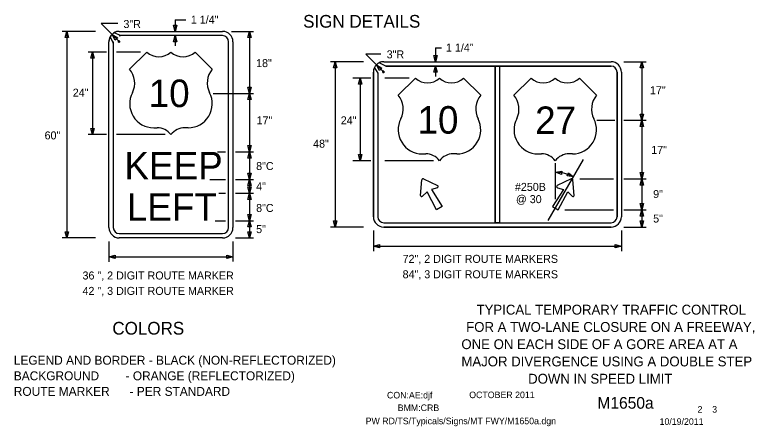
# Model space of a CAD drawing. Extents: x 16512 to 19509, y 5761 to 6974.
# Drawn here: x 17768 to 18466, y 5932 to 6320 of the extents above; entities that cross this region are included whole.
import ezdxf

# ---------------------------------------------------------------- set-up
doc = ezdxf.new("R2010")
doc.units = 0
for name, color, linetype in [('BORDER', 7, 'Continuous'), ('BORDER_SIGNAL_WO', 7, 'Continuous'), ('TRAFFIC_SIGNS_PR', 7, 'Continuous'), ('TYPICAL_EX', 7, 'Continuous'), ('TYPICAL_TEXT_DIMEN_PR', 7, 'Continuous')]:
    doc.layers.add(name, color=color, linetype=linetype)

msp = doc.modelspace()

# ---------------------------------------------------------------- linework, layer by layer
at = {"layer": 'TRAFFIC_SIGNS_PR'}
for p, q in [((17859.5, 6300.96), (17858.5, 6299.45)), ((17868.29, 6300.52), (17862.19, 6303.27)), ((17867.09, 6304.58), (17964.59, 6304.58)), ((17857.34, 6119.33), (17857.34, 6294.83)), ((17858.53, 6299.39), (17861.4, 6293.35)), ((17861.4, 6294.83), (17861.4, 6119.33)), ((17964.59, 6300.52), (17867.09, 6300.52)), ((17970.27, 6119.33), (17970.27, 6294.83)), ((17974.34, 6294.83), (17974.34, 6119.33)), ((18118.56, 6271.83), (18112.33, 6274.85)), ((18116.61, 6275.88), (18331.11, 6275.88)), ((18116.61, 6275.88), (18331.11, 6275.88)), ((18106.86, 6266.13), (18106.86, 6129.63)), ((18106.86, 6129.63), (18106.86, 6266.13)), ((18107.78, 6270.14), (18110.91, 6265.1)), ((18118.55, 6271.82), (18221.83, 6271.82)), ((18331.11, 6271.82), (18118.55, 6271.82)), ((18221.83, 6271.82), (18221.83, 6123.95)), ((18225.89, 6271.82), (18225.89, 6123.95)), ((18225.89, 6271.82), (18331.11, 6271.82)), ((18336.8, 6266.13), (18336.8, 6220.38)), ((18336.8, 6129.63), (18336.8, 6266.13)), ((18340.86, 6266.13), (18340.86, 6129.63)), ((18340.86, 6266.13), (18340.86, 6129.63)), ((18110.92, 6265.08), (18110.92, 6129.63)), ((18110.92, 6265.08), (18110.92, 6129.63)), ((18336.8, 6220.38), (18336.8, 6129.63)), ((18151.46, 6149.74), (18152.61, 6164.46)), ((18154.12, 6165.33), (18167.44, 6158.97)), ((18293.59, 6165.33), (18280.28, 6158.97)), ((18296.26, 6149.74), (18295.1, 6164.46)), ((18116.61, 6123.95), (18331.11, 6123.95)), ((18116.61, 6119.88), (18331.11, 6119.88)), ((18331.11, 6119.88), (18116.61, 6119.88)), ((17867.09, 6113.64), (17964.59, 6113.64)), ((17964.59, 6109.58), (17867.09, 6109.58))]:
    msp.add_line(p, q, dxfattribs=at)
for points in [[(18118.55, 6271.82), (18118.53, 6271.83)], [(18110.91, 6265.1), (18110.92, 6265.08)], [(18167.28, 6157), (18161.55, 6155.42), (18171.77, 6139.25), (18166.37, 6136.13), (18157.48, 6153.07), (18153.25, 6148.9)], [(18280.44, 6157), (18286.16, 6155.42), (18275.95, 6139.25), (18281.34, 6136.13), (18290.24, 6153.07), (18294.46, 6148.9)]]:
    msp.add_lwpolyline(points, dxfattribs=at)
msp.add_lwpolyline([(18221.83, 6271.82), (18225.89, 6271.82), (18225.89, 6123.95), (18221.83, 6123.95)], close=True, dxfattribs=at)
for centre, radius, start, end in [((17867.09, 6294.83), 9.75, 90, 180), ((17866.5, 6297.01), 7.6, 85.58319, 124.53531), ((17964.59, 6294.83), 9.75, 0, 90), ((17864.37, 6295.43), 7.06, 145.86811, 184.82317), ((17855.94, 6294.09), 5.51, 352.24294, 7.75653), ((17867.69, 6304.95), 4.47, 262.2432, 277.7568), ((17964.59, 6294.83), 5.69, 0, 90), ((18116.61, 6266.13), 9.75, 90, 180), ((18116.61, 6266.13), 9.75, 90, 180), ((18115.93, 6269.32), 6.6, 84.11162, 123.06374), ((18331.11, 6266.13), 9.75, 0, 90), ((18331.11, 6266.13), 9.75, 0, 90), ((18112.99, 6266.84), 6.17, 147.60925, 186.56283), ((18117.55, 6279), 7.24, 277.81035, 278.05403), ((18331.11, 6266.13), 5.69, 0, 89.99421), ((18331.11, 6266.13), 5.69, 0, 90), ((18153.67, 6164.37), 1.06, 64.48226, 175.51774), ((18294.05, 6164.37), 1.06, 4.48226, 115.51774), ((18166.98, 6158.02), 1.06, 285.9885, 64.48226), ((18280.73, 6158.02), 1.06, 115.51774, 254.0115), ((18152.52, 6149.66), 1.06, 175.51775, 314.01151), ((18295.2, 6149.66), 1.06, 225.98849, 4.48225), ((18116.61, 6129.63), 9.75, 180, 270), ((18116.61, 6129.63), 9.75, 180, 270), ((18116.61, 6129.63), 5.69, 180, 270), ((18116.61, 6129.63), 5.69, 180, 270), ((18331.11, 6129.63), 9.75, 270, 0), ((18331.11, 6129.63), 5.69, 270, 0), ((18331.11, 6129.63), 9.75, 270, 0), ((18331.11, 6129.63), 5.69, 270, 0), ((17867.09, 6119.33), 9.75, 180, 270), ((17867.09, 6119.33), 5.69, 180, 270), ((17964.59, 6119.33), 5.69, 270, 0), ((17964.59, 6119.33), 9.75, 270, 0)]:
    msp.add_arc(centre, radius, start, end, dxfattribs=at)
at = {"layer": 'TYPICAL_EX'}
for p, q in [((17876.84, 6268.84), (17893.09, 6285.09)), ((17954.84, 6268.84), (17938.59, 6285.09)), ((18130.22, 6244.22), (18146.47, 6260.47)), ((18208.22, 6244.22), (18191.97, 6260.47)), ((18239.5, 6244.22), (18255.75, 6260.47)), ((18317.5, 6244.22), (18301.25, 6260.47)), ((17899.56, 6213.54), (17902.81, 6213.54)), ((17932.11, 6213.54), (17928.86, 6213.54)), ((18152.95, 6188.93), (18156.2, 6188.93)), ((18185.49, 6188.93), (18182.24, 6188.93)), ((18262.22, 6188.93), (18265.47, 6188.93)), ((18294.77, 6188.93), (18291.52, 6188.93))]:
    msp.add_line(p, q, dxfattribs=at)
for centre, radius, start, end in [((17904.46, 6296.92), 16.42, 226.14041, 313.85958), ((17927.21, 6296.92), 16.42, 226.14042, 313.85959), ((17861.44, 6255.82), 20.16, 333.09768, 40.19361), ((17970.24, 6255.82), 20.16, 139.80639, 206.90233), ((18157.85, 6272.31), 16.42, 226.14041, 313.85958), ((18180.59, 6272.31), 16.42, 226.14042, 313.85959), ((18267.12, 6272.31), 16.42, 226.14041, 313.85958), ((18289.87, 6272.31), 16.42, 226.14042, 313.85959), ((17899.6, 6236.27), 22.73, 152.6698, 269.90132), ((17932.07, 6236.27), 22.73, 270.09868, 27.3302), ((18114.82, 6231.21), 20.16, 333.09768, 40.19361), ((18223.62, 6231.21), 20.16, 139.80639, 206.90233), ((18224.1, 6231.21), 20.16, 333.09768, 40.19361), ((18332.9, 6231.21), 20.16, 139.80639, 206.90233), ((18152.99, 6211.66), 22.73, 152.6698, 269.90132), ((18185.45, 6211.66), 22.73, 270.09868, 27.3302), ((18262.27, 6211.66), 22.73, 152.6698, 269.90132), ((18294.73, 6211.66), 22.73, 270.09868, 27.3302), ((17902.85, 6197.26), 16.28, 37.1038, 90.13853), ((17928.82, 6197.26), 16.28, 89.86147, 142.8962), ((18156.24, 6172.65), 16.28, 37.1038, 90.13853), ((18182.2, 6172.65), 16.28, 89.86147, 142.8962), ((18265.52, 6172.65), 16.28, 37.1038, 90.13853), ((18291.48, 6172.65), 16.28, 89.86147, 142.8962)]:
    msp.add_arc(centre, radius, start, end, dxfattribs=at)
at = {"layer": 'TYPICAL_TEXT_DIMEN_PR'}
for p, q in [((17919.81, 6315.34), (17919.81, 6304.58)), ((17919.81, 6315.34), (17929.91, 6315.34)), ((17865.71, 6311.86), (17850.05, 6311.86)), ((17850.05, 6311.86), (17860.29, 6301.63)), ((17919.81, 6304.58), (17918.24, 6310.44)), ((17918.24, 6310.44), (17919.81, 6310.44)), ((17919.81, 6310.44), (17921.38, 6310.44)), ((17921.38, 6310.44), (17919.81, 6304.58)), ((17844.51, 6304.58), (17813.21, 6304.58)), ((17815.98, 6298.72), (17817.55, 6304.58)), ((17817.55, 6304.58), (17817.55, 6109.58)), ((17817.55, 6304.58), (17819.12, 6298.72)), ((17860.29, 6301.63), (17866.85, 6295.07)), ((17863.32, 6296.37), (17860.29, 6301.63)), ((17860.29, 6301.63), (17865.54, 6298.6)), ((17972.88, 6304.58), (17993.84, 6304.58)), ((17988.37, 6298.72), (17989.94, 6304.58)), ((17989.94, 6304.58), (17989.94, 6246.08)), ((17989.94, 6304.58), (17991.51, 6298.72)), ((17817.55, 6298.72), (17815.98, 6298.72)), ((17819.12, 6298.72), (17817.55, 6298.72)), ((17864.43, 6297.49), (17863.32, 6296.37)), ((17865.54, 6298.6), (17864.43, 6297.49)), ((17865.64, 6295.07), (17868.05, 6295.07)), ((17866.85, 6293.86), (17866.85, 6296.28)), ((17918.28, 6294.66), (17919.86, 6300.52)), ((17919.86, 6294.66), (17918.28, 6294.66)), ((17919.86, 6300.52), (17919.86, 6290.77)), ((17919.86, 6300.52), (17921.43, 6294.66)), ((17921.43, 6294.66), (17919.86, 6294.66)), ((17989.94, 6298.72), (17988.37, 6298.72)), ((17991.51, 6298.72), (17989.94, 6298.72)), ((18165.47, 6289.03), (18165.47, 6275.88)), ((18165.47, 6289.03), (18170.99, 6289.03)), ((17854.96, 6285.08), (17837.84, 6285.08)), ((17840.16, 6279.22), (17841.73, 6285.08)), ((17841.73, 6285.08), (17841.73, 6207.08)), ((17841.73, 6285.08), (17843.3, 6279.22)), ((17887.2, 6285.08), (17864.33, 6285.08)), ((18113.75, 6283.17), (18099.57, 6283.17)), ((18099.57, 6283.17), (18109.72, 6273.02)), ((18165.47, 6275.88), (18163.89, 6281.74)), ((18163.89, 6281.74), (18165.47, 6281.74)), ((18165.47, 6281.74), (18167.04, 6281.74)), ((18167.04, 6281.74), (18165.47, 6275.88)), ((17841.73, 6279.22), (17840.16, 6279.22)), ((17843.3, 6279.22), (17841.73, 6279.22)), ((18097.62, 6275.88), (18066.33, 6275.88)), ((18069.1, 6270.02), (18070.67, 6275.88)), ((18070.67, 6275.88), (18070.67, 6119.88)), ((18070.67, 6275.88), (18072.24, 6270.02)), ((18109.72, 6273.02), (18116.37, 6266.37)), ((18112.76, 6267.76), (18109.72, 6273.02)), ((18109.72, 6273.02), (18114.98, 6269.99)), ((18343.23, 6275.88), (18364.19, 6275.88)), ((18358.72, 6270.02), (18360.29, 6275.88)), ((18360.29, 6275.88), (18360.29, 6220.63)), ((18360.29, 6275.88), (18361.86, 6270.02)), ((18070.67, 6270.02), (18069.1, 6270.02)), ((18072.24, 6270.02), (18070.67, 6270.02)), ((18113.87, 6268.88), (18112.76, 6267.76)), ((18114.98, 6269.99), (18113.87, 6268.88)), ((18115.16, 6266.37), (18117.58, 6266.37)), ((18116.37, 6265.16), (18116.37, 6267.58)), ((18163.94, 6265.96), (18165.51, 6271.82)), ((18163.94, 6265.96), (18165.51, 6271.82)), ((18165.51, 6271.82), (18165.51, 6262.07)), ((18165.51, 6271.82), (18167.08, 6265.96)), ((18165.51, 6271.82), (18167.08, 6265.96)), ((18360.29, 6270.02), (18358.72, 6270.02)), ((18361.86, 6270.02), (18360.29, 6270.02)), ((18104.49, 6260.47), (18087.36, 6260.47)), ((18092.65, 6254.61), (18094.23, 6260.47)), ((18094.23, 6260.47), (18094.23, 6182.47)), ((18094.23, 6260.47), (18095.8, 6254.61)), ((18140.59, 6260.47), (18117.71, 6260.47)), ((18165.51, 6265.96), (18163.94, 6265.96)), ((18165.51, 6265.96), (18163.94, 6265.96)), ((18167.08, 6265.96), (18165.51, 6265.96)), ((18167.08, 6265.96), (18165.51, 6265.96)), ((18094.23, 6254.61), (18092.65, 6254.61)), ((18095.8, 6254.61), (18094.23, 6254.61)), ((17955.73, 6246.08), (17993.84, 6246.08)), ((17989.94, 6246.08), (17988.37, 6251.94)), ((17988.37, 6251.94), (17989.94, 6251.94)), ((17988.37, 6240.22), (17989.94, 6246.08)), ((17989.94, 6251.94), (17991.51, 6251.94)), ((17991.51, 6251.94), (17989.94, 6246.08)), ((17989.94, 6246.08), (17989.94, 6190.83)), ((17989.94, 6246.08), (17991.51, 6240.22)), ((17989.94, 6240.22), (17988.37, 6240.22)), ((17991.51, 6240.22), (17989.94, 6240.22)), ((18360.29, 6220.63), (18358.72, 6226.49)), ((18358.72, 6226.49), (18360.29, 6226.49)), ((18360.29, 6226.49), (18361.86, 6226.49)), ((18361.86, 6226.49), (18360.29, 6220.63)), ((18317.67, 6220.63), (18334.82, 6220.63)), ((18343.23, 6220.63), (18364.19, 6220.63)), ((18358.72, 6214.77), (18360.29, 6220.63)), ((18360.29, 6220.63), (18360.29, 6165.38)), ((18360.29, 6220.63), (18361.86, 6214.77)), ((17841.73, 6207.08), (17840.16, 6212.94)), ((17840.16, 6212.94), (17841.73, 6212.94)), ((17841.73, 6212.94), (17843.3, 6212.94)), ((17843.3, 6212.94), (17841.73, 6207.08)), ((18360.29, 6214.77), (18358.72, 6214.77)), ((18361.86, 6214.77), (18360.29, 6214.77)), ((17854.96, 6207.08), (17837.84, 6207.08)), ((17910.33, 6207.08), (17864.33, 6207.08)), ((17989.94, 6190.83), (17988.37, 6196.69)), ((17988.37, 6196.69), (17989.94, 6196.69)), ((17989.94, 6196.69), (17991.51, 6196.69)), ((17991.51, 6196.69), (17989.94, 6190.83)), ((17959.66, 6190.83), (17967.35, 6190.83)), ((17976.71, 6190.83), (17993.84, 6190.83)), ((17988.37, 6184.97), (17989.94, 6190.83)), ((17989.94, 6190.83), (17989.94, 6164.83)), ((17989.94, 6190.83), (17991.51, 6184.97)), ((17989.94, 6184.97), (17988.37, 6184.97)), ((17991.51, 6184.97), (17989.94, 6184.97)), ((18104.49, 6182.47), (18087.36, 6182.47)), ((18094.23, 6182.47), (18092.65, 6188.33)), ((18092.65, 6188.33), (18094.23, 6188.33)), ((18094.23, 6188.33), (18095.8, 6188.33)), ((18095.8, 6188.33), (18094.23, 6182.47)), ((18163.71, 6182.47), (18117.71, 6182.47)), ((18271.89, 6125.98), (18305.13, 6183.57)), ((18278.65, 6146.14), (18278.65, 6180.13)), ((17989.94, 6164.83), (17988.37, 6170.69)), ((17988.37, 6170.69), (17989.94, 6170.69)), ((17989.94, 6170.69), (17991.51, 6170.69)), ((17991.51, 6170.69), (17989.94, 6164.83)), ((18278.67, 6171.58), (18284.67, 6172.54)), ((18284.35, 6169.41), (18278.67, 6171.58)), ((18284.51, 6170.97), (18284.35, 6169.41)), ((18284.67, 6172.54), (18284.51, 6170.97)), ((18289.66, 6168.25), (18290.34, 6169.67)), ((18290.34, 6169.67), (18291.03, 6171.08)), ((18291.03, 6171.08), (18295.62, 6167.12)), ((18360.29, 6165.38), (18358.72, 6171.24)), ((18358.72, 6171.24), (18360.29, 6171.24)), ((18360.29, 6171.24), (18361.86, 6171.24)), ((18361.86, 6171.24), (18360.29, 6165.38)), ((17952.65, 6164.83), (17967.35, 6164.83)), ((17976.71, 6164.83), (17993.84, 6164.83)), ((17988.37, 6158.97), (17989.94, 6164.83)), ((17989.94, 6164.83), (17989.94, 6151.83)), ((17989.94, 6164.83), (17991.51, 6158.97)), ((18295.62, 6167.12), (18289.66, 6168.25)), ((18301.6, 6165.38), (18333.47, 6165.38)), ((18343.23, 6165.38), (18364.19, 6165.38)), ((18358.72, 6159.52), (18360.29, 6165.38)), ((18360.29, 6165.38), (18360.29, 6136.13)), ((18360.29, 6165.38), (18361.86, 6159.52)), ((17989.94, 6158.97), (17988.37, 6158.97)), ((17989.94, 6151.83), (17988.37, 6157.69)), ((17988.37, 6157.69), (17989.94, 6157.69)), ((17991.51, 6158.97), (17989.94, 6158.97)), ((17989.94, 6157.69), (17991.51, 6157.69)), ((17991.51, 6157.69), (17989.94, 6151.83)), ((18360.29, 6159.52), (18358.72, 6159.52)), ((18361.86, 6159.52), (18360.29, 6159.52)), ((17961, 6151.83), (17967.35, 6151.83)), ((17976.71, 6151.83), (17993.84, 6151.83)), ((17988.37, 6145.97), (17989.94, 6151.83)), ((17989.94, 6151.83), (17989.94, 6125.83)), ((17989.94, 6151.83), (17991.51, 6145.97)), ((17989.94, 6145.97), (17988.37, 6145.97)), ((17991.51, 6145.97), (17989.94, 6145.97)), ((18360.29, 6136.13), (18358.72, 6141.99)), ((18358.72, 6141.99), (18360.29, 6141.99)), ((18360.29, 6141.99), (18361.86, 6141.99)), ((18361.86, 6141.99), (18360.29, 6136.13)), ((18287.46, 6136.13), (18333.47, 6136.13)), ((18343.23, 6136.13), (18364.19, 6136.13)), ((18358.72, 6130.27), (18360.29, 6136.13)), ((18360.29, 6136.13), (18360.29, 6119.88)), ((18360.29, 6136.13), (18361.86, 6130.27)), ((17989.94, 6125.83), (17988.37, 6131.69)), ((17988.37, 6131.69), (17989.94, 6131.69)), ((17989.94, 6131.69), (17991.51, 6131.69)), ((17991.51, 6131.69), (17989.94, 6125.83)), ((18360.29, 6130.27), (18358.72, 6130.27)), ((18361.86, 6130.27), (18360.29, 6130.27)), ((17957.5, 6125.83), (17967.35, 6125.83)), ((17976.71, 6125.83), (17993.84, 6125.83)), ((17988.37, 6119.97), (17989.94, 6125.83)), ((17989.94, 6119.97), (17988.37, 6119.97)), ((17989.94, 6125.83), (17989.94, 6109.58)), ((17989.94, 6125.83), (17991.51, 6119.97)), ((17991.51, 6119.97), (17989.94, 6119.97)), ((18097.62, 6119.88), (18066.33, 6119.88)), ((18070.67, 6119.88), (18069.1, 6125.74)), ((18069.1, 6125.74), (18070.67, 6125.74)), ((18070.67, 6125.74), (18072.24, 6125.74)), ((18072.24, 6125.74), (18070.67, 6119.88)), ((18343.23, 6119.88), (18360.36, 6119.88)), ((18343.23, 6119.88), (18364.19, 6119.88)), ((18343.23, 6119.88), (18360.36, 6119.88)), ((18360.29, 6119.88), (18358.72, 6125.74)), ((18358.72, 6125.74), (18360.29, 6125.74)), ((18360.29, 6125.74), (18361.86, 6125.74)), ((18361.86, 6125.74), (18360.29, 6119.88)), ((17817.55, 6109.58), (17815.98, 6115.44)), ((17815.98, 6115.44), (17817.55, 6115.44)), ((17817.55, 6115.44), (17819.12, 6115.44)), ((17819.12, 6115.44), (17817.55, 6109.58)), ((17989.94, 6109.58), (17988.37, 6115.44)), ((17988.37, 6115.44), (17989.94, 6115.44)), ((17989.94, 6115.44), (17991.51, 6115.44)), ((17991.51, 6115.44), (17989.94, 6109.58)), ((18106.86, 6116.54), (18106.86, 6096.98)), ((18340.86, 6116.54), (18340.86, 6096.98)), ((17844.51, 6109.58), (17813.21, 6109.58)), ((17857.34, 6106.24), (17857.34, 6086.89)), ((17974.34, 6106.24), (17974.34, 6087.34)), ((17976.71, 6109.58), (17993.84, 6109.58)), ((18106.86, 6101.91), (18112.72, 6103.48)), ((18106.86, 6101.91), (18340.86, 6101.91)), ((18112.72, 6100.34), (18106.86, 6101.91)), ((18112.72, 6103.48), (18112.72, 6101.91)), ((18112.72, 6101.91), (18112.72, 6100.34)), ((18335, 6101.91), (18335, 6103.48)), ((18335, 6103.48), (18340.86, 6101.91)), ((18340.86, 6101.91), (18335, 6100.34)), ((18335, 6100.34), (18335, 6101.91)), ((17857.34, 6091.61), (17863.2, 6093.18)), ((17857.34, 6091.61), (17974.34, 6091.61)), ((17863.2, 6090.04), (17857.34, 6091.61)), ((17863.2, 6093.18), (17863.2, 6091.61)), ((17863.2, 6091.61), (17863.2, 6090.04)), ((17968.47, 6091.61), (17968.47, 6093.18)), ((17968.47, 6093.18), (17974.34, 6091.61)), ((17974.34, 6091.61), (17968.47, 6090.04)), ((17968.47, 6090.04), (17968.47, 6091.61))]:
    msp.add_line(p, q, dxfattribs=at)
msp.add_arc((18278.84, 6137.14), 34.39, 60.74521, 90.32117, dxfattribs=at)

# ---------------------------------------------------------------- texts
at = {"layer": 'BORDER'}
for s, p in [('TYPICAL TEMPORARY TRAFFIC CONTROL', (18204.21, 6037.21)), ('FOR A TWO-LANE CLOSURE ON A FREEWAY,', (18194.41, 6020.91)), ('ONE ON EACH SIDE OF A GORE AREA AT A ', (18189.92, 6004.62)), ('MAJOR DIVERGENCE USING A DOUBLE STEP ', (18189.92, 5988.32)), ('DOWN IN SPEED LIMIT', (18252.92, 5972.02))]:
    msp.add_text(s, height=9.3, dxfattribs=at).set_placement(p)
at = {"layer": 'BORDER_SIGNAL_WO'}
for s, height, p in [('CON:AE:djf  ', 6.2, (18119.69, 5958.06)), ('    OCTOBER 2011    ', 6.2, (18188.08, 5958.34)), ('    M1650a   ', 11, (18301.86, 5948.38)), ('BMM:CRB   ', 6.2, (18129.81, 5946.17)), (' 2    3 ', 6.2, (18410.45, 5944.7)), ('PW RD/TS/Typicals/Signs/MT FWY/M1650a.dgn      ', 6.2, (18099.55, 5933.71)), ('10/19/2011    ', 6.2, (18376.93, 5933.13))]:
    msp.add_text(s, height=height, dxfattribs=at).set_placement(p)
at = {"layer": 'TRAFFIC_SIGNS_PR'}
for s, p in [('10', (17894.81, 6233.08)), ('10', (18148.46, 6208.01)), ('27', (18259.47, 6207.65)), ('KEEP', (17871.94, 6164.83)), ('LEFT', (17874.17, 6125.83))]:
    msp.add_text(s, height=26, dxfattribs=at).set_placement(p)
at = {"layer": 'TYPICAL_TEXT_DIMEN_PR'}
for s, height, p in [('3"R', 7.55, (17870.98, 6307.74)), ('1 1/4"', 7.55, (17934.61, 6311.84)), ('SIGN DETAILS', 12, (18040.56, 6308.05)), ('1 1/4"', 7.55, (18175.39, 6285.46)), ('3"R', 7.55, (18119.39, 6279.09)), ('18"', 7.55, (17996.18, 6270.85)), ('17"', 7.55, (18367.87, 6245.24)), ('24"', 7.55, (17823.18, 6242.97)), ('17"', 7.55, (17996.64, 6216.81)), ('24"', 7.55, (18076.08, 6216.8)), ('60"', 7.55, (17796.58, 6202.6)), ('48"', 7.55, (18049.97, 6194.78)), ('17"', 7.55, (18369.07, 6188.89)), ('8"C', 7.55, (17996.21, 6173.69)), ('4" ', 7.55, (17996.21, 6154.43)), ('#250B', 7.55, (18240.42, 6153.98)), ('9"', 7.55, (18370.85, 6147.23)), ('@ 30', 7.55, (18241.36, 6142.43)), ('8"C', 7.55, (17996.21, 6134.1)), ('5"', 7.55, (18370.85, 6124.13)), ('5" ', 7.55, (17996.21, 6114.13)), ('72", 2 DIGIT ROUTE MARKERS', 7.55, (18134.44, 6086.05)), ('36 ", 2 DIGIT ROUTE MARKER', 7.55, (17832.38, 6070.35)), ('84", 3 DIGIT ROUTE MARKERS', 7.55, (18134.44, 6071.5)), ('42 ", 3 DIGIT ROUTE MARKER', 7.55, (17832.38, 6055.8)), ('COLORS', 12, (17860.53, 6018.33)), ('LEGEND AND BORDER - BLACK (NON-REFLECTORIZED)', 8.4, (17767.53, 5989.92)), ('BACKGROUND        - ORANGE (REFLECTORIZED)', 8.4, (17767.53, 5975.22)), ('ROUTE MARKER      - PER STANDARD', 8.4, (17767.53, 5960.52))]:
    msp.add_text(s, height=height, dxfattribs=at).set_placement(p)

doc.saveas('drawing.dxf')
